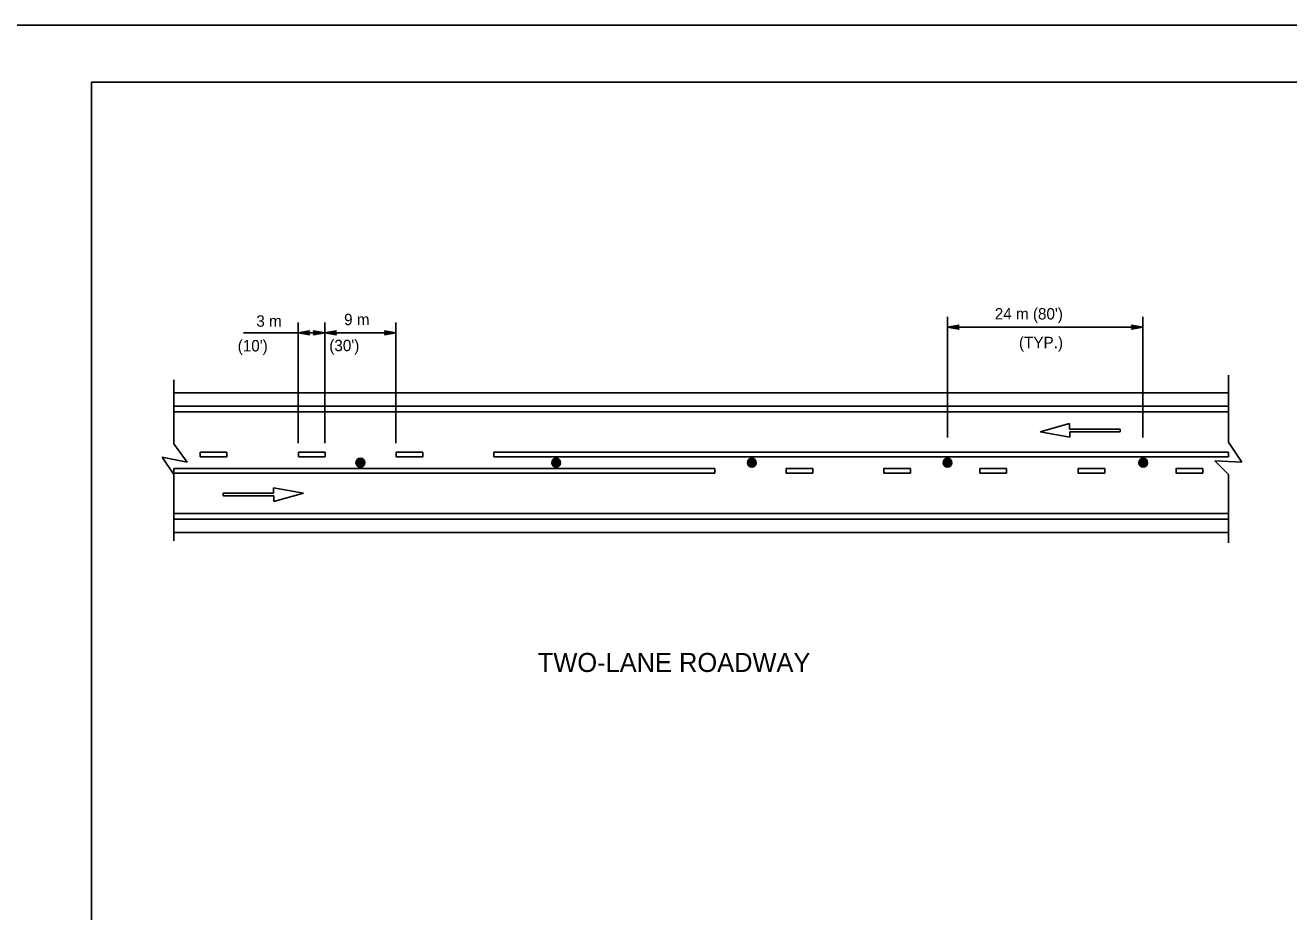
# Model space of a CAD drawing. Extents: x 639362 to 641108, y 298458 to 299646.
# Drawn here: x 640225.9 to 640558.2, y 299412.4 to 299645.6 of the extents above; entities that cross this region are included whole.
import ezdxf

# ---------------------------------------------------------------- set-up
doc = ezdxf.new("R2010")
doc.units = 0
for name, color, linetype in [('1', 7, 'Continuous'), ('2', 7, 'Continuous'), ('3', 7, 'Continuous'), ('PLT-BNDY', 7, 'Continuous')]:
    doc.layers.add(name, color=color, linetype=linetype)

# ---------------------------------------------------------------- blocks, each defined once
blk = doc.blocks.new('RARROW')
at = {"layer": '3'}
blk.add_lwpolyline([(-2.2695, 0.285), (-2.184875, 0.12075), (0, 0), (-2.2695, 0.285), (-2.38575, 0.384625), (0, 0), (-2.183125, -0.108), (-2.262875, -0.2705), (0, 0), (-2.38575, -0.379125), (-2.262875, -0.2705)], dxfattribs=at)

msp = doc.modelspace()

# ---------------------------------------------------------------- linework, layer by layer
at = {"layer": '1'}
for q in [(641029.31, 299630.63), (640243.31, 299066.63)]:
    msp.add_line((640243.31, 299630.63), q, dxfattribs=at)
at = {"layer": '2'}
for p, q in [((640468.44, 299537.15), (640468.44, 299568.92)), ((640519.83, 299537.15), (640519.83, 299568.92)), ((640283.3, 299564.71), (640304.65, 299564.71)), ((640297.63, 299535.66), (640297.63, 299567.43)), ((640304.65, 299535.66), (640304.65, 299567.43)), ((640304.65, 299564.71), (640323.37, 299564.71)), ((640323.37, 299535.66), (640323.37, 299567.43)), ((640519.83, 299566.2), (640468.44, 299566.2)), ((640264.93, 299552.35), (640264.93, 299535.55)), ((640542.37, 299553.63), (640542.37, 299535.95)), ((640264.93, 299548.92), (640542.37, 299548.92)), ((640264.93, 299545.42), (640542.37, 299545.42)), ((640264.93, 299543.92), (640542.37, 299543.92)), ((640500.53, 299540.83), (640492.81, 299538.71)), ((640492.81, 299538.71), (640500.61, 299537.24)), ((640500.53, 299539.38), (640500.53, 299540.83)), ((640513.86, 299539.38), (640500.53, 299539.38)), ((640500.61, 299537.24), (640500.61, 299538.68)), ((640500.61, 299538.68), (640513.86, 299538.68)), ((640513.86, 299538.68), (640513.86, 299539.38)), ((640268.42, 299530.66), (640264.93, 299535.55)), ((640545.86, 299530.66), (640542.37, 299535.95)), ((640264.93, 299527.43), (640261.88, 299532.01)), ((640261.88, 299532.01), (640268.42, 299530.66)), ((640278.91, 299533.35), (640271.89, 299533.35)), ((640271.89, 299533.35), (640278.91, 299533.33)), ((640278.91, 299532.13), (640278.91, 299533.35)), ((640304.76, 299533.35), (640297.74, 299533.35)), ((640297.74, 299533.35), (640304.76, 299533.33)), ((640304.76, 299532.13), (640304.76, 299533.35)), ((640330.42, 299533.35), (640323.41, 299533.35)), ((640323.41, 299533.35), (640330.42, 299533.33)), ((640330.42, 299532.13), (640330.42, 299533.35)), ((640542.37, 299533.33), (640349.14, 299533.33)), ((640349.14, 299533.33), (640349.14, 299532.13)), ((640349.14, 299532.13), (640542.37, 299532.13)), ((640542.37, 299532.13), (640542.37, 299533.33)), ((640407.24, 299529.02), (640264.97, 299529.02)), ((640264.97, 299529.02), (640264.97, 299527.82)), ((640407.24, 299527.82), (640407.24, 299529.02)), ((640433, 299529.04), (640425.98, 299529.04)), ((640425.98, 299529.04), (640433, 299529.02)), ((640433, 299527.82), (640433, 299529.04)), ((640458.68, 299529.04), (640451.66, 299529.04)), ((640451.66, 299529.04), (640458.68, 299529.02)), ((640458.68, 299527.82), (640458.68, 299529.04)), ((640484, 299529.04), (640476.98, 299529.04)), ((640476.98, 299529.04), (640484, 299529.02)), ((640484, 299527.82), (640484, 299529.04)), ((640509.8, 299529.04), (640502.78, 299529.04)), ((640502.78, 299529.04), (640509.8, 299529.02)), ((640509.8, 299527.82), (640509.8, 299529.04)), ((640535.59, 299529.04), (640528.57, 299529.04)), ((640528.57, 299529.04), (640535.59, 299529.02)), ((640535.59, 299527.82), (640535.59, 299529.04)), ((640542.37, 299527.43), (640538.76, 299531.05)), ((640538.76, 299531.05), (640545.86, 299530.66)), ((640264.93, 299527.43), (640264.93, 299509.98)), ((640264.97, 299527.82), (640407.24, 299527.82)), ((640542.37, 299527.43), (640542.37, 299509.46)), ((640291.19, 299522.54), (640277.95, 299522.54)), ((640277.95, 299522.54), (640277.95, 299521.84)), ((640277.95, 299521.84), (640291.27, 299521.84)), ((640299, 299522.51), (640291.19, 299523.98)), ((640291.19, 299523.98), (640291.19, 299522.54)), ((640291.27, 299520.39), (640299, 299522.51)), ((640291.27, 299521.84), (640291.27, 299520.39)), ((640264.93, 299517.23), (640542.37, 299517.23)), ((640264.93, 299515.73), (640542.37, 299515.73)), ((640264.93, 299512.23), (640542.37, 299512.23))]:
    msp.add_line(p, q, dxfattribs=at)
for points in [[(640278.91, 299533.33), (640271.89, 299533.33), (640271.89, 299532.13), (640278.91, 299532.13)], [(640304.76, 299533.33), (640297.74, 299533.33), (640297.74, 299532.13), (640304.76, 299532.13)], [(640330.42, 299533.33), (640323.41, 299533.33), (640323.41, 299532.13), (640330.42, 299532.13)], [(640433, 299529.02), (640425.98, 299529.02), (640425.98, 299527.82), (640433, 299527.82)], [(640458.68, 299529.02), (640451.66, 299529.02), (640451.66, 299527.82), (640458.68, 299527.82)], [(640484, 299529.02), (640476.98, 299529.02), (640476.98, 299527.82), (640484, 299527.82)], [(640509.8, 299529.02), (640502.78, 299529.02), (640502.78, 299527.82), (640509.8, 299527.82)], [(640535.59, 299529.02), (640528.57, 299529.02), (640528.57, 299527.82), (640535.59, 299527.82)]]:
    msp.add_lwpolyline(points, dxfattribs=at)
for centre, radius in [((640314, 299530.57), 1.15), ((640314, 299530.57), 1.07), ((640314, 299530.57), 0.985), ((640314, 299530.57), 0.904), ((640314, 299530.57), 0.822), ((640365.49, 299530.57), 1.15), ((640365.49, 299530.57), 1.07), ((640365.49, 299530.57), 0.985), ((640365.49, 299530.57), 0.904), ((640365.49, 299530.57), 0.822), ((640416.97, 299530.57), 1.15), ((640416.97, 299530.57), 1.07), ((640416.97, 299530.57), 0.985), ((640416.97, 299530.57), 0.904), ((640416.97, 299530.57), 0.822), ((640468.45, 299530.57), 1.15), ((640468.45, 299530.57), 1.07), ((640468.45, 299530.57), 0.985), ((640468.45, 299530.57), 0.904), ((640468.45, 299530.57), 0.822), ((640519.94, 299530.57), 1.15), ((640519.94, 299530.57), 1.07), ((640519.94, 299530.57), 0.985), ((640519.94, 299530.57), 0.904), ((640519.94, 299530.57), 0.822), ((640314, 299530.57), 0.741), ((640314, 299530.57), 0.659), ((640314, 299530.57), 0.578), ((640314, 299530.57), 0.496), ((640314, 299530.57), 0.414), ((640314, 299530.57), 0.333), ((640314, 299530.57), 0.251), ((640314, 299530.57), 0.17), ((640314, 299530.57), 0.0881), ((640365.49, 299530.57), 0.741), ((640365.49, 299530.57), 0.659), ((640365.49, 299530.57), 0.578), ((640365.49, 299530.57), 0.496), ((640365.49, 299530.57), 0.414), ((640365.49, 299530.57), 0.333), ((640365.49, 299530.57), 0.251), ((640365.49, 299530.57), 0.17), ((640365.49, 299530.57), 0.0881), ((640416.97, 299530.57), 0.741), ((640416.97, 299530.57), 0.659), ((640416.97, 299530.57), 0.578), ((640416.97, 299530.57), 0.496), ((640416.97, 299530.57), 0.414), ((640416.97, 299530.57), 0.333), ((640416.97, 299530.57), 0.251), ((640416.97, 299530.57), 0.17), ((640416.97, 299530.57), 0.0881), ((640468.45, 299530.57), 0.741), ((640468.45, 299530.57), 0.659), ((640468.45, 299530.57), 0.578), ((640468.45, 299530.57), 0.496), ((640468.45, 299530.57), 0.414), ((640468.45, 299530.57), 0.333), ((640468.45, 299530.57), 0.251), ((640468.45, 299530.57), 0.17), ((640468.45, 299530.57), 0.0881), ((640519.94, 299530.57), 0.741), ((640519.94, 299530.57), 0.659), ((640519.94, 299530.57), 0.578), ((640519.94, 299530.57), 0.496), ((640519.94, 299530.57), 0.414), ((640519.94, 299530.57), 0.333), ((640519.94, 299530.57), 0.251), ((640519.94, 299530.57), 0.17), ((640519.94, 299530.57), 0.0881)]:
    msp.add_circle(centre, radius, dxfattribs=at)
at = {"layer": 'PLT-BNDY'}
msp.add_lwpolyline([(640203.31, 299645.63), (641044.31, 299645.63), (641044.31, 299051.63), (640203.31, 299051.63)], close=True, dxfattribs=at)

# ---------------------------------------------------------------- block references
at = {"layer": '2', "xscale": 1.2574347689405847, "yscale": 1.3092961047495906, "rotation": 180}
for p in [(640297.63, 299564.71), (640304.65, 299564.71), (640468.44, 299566.2)]:
    msp.add_blockref('RARROW', p, dxfattribs=at)
at = {"layer": '2', "xscale": 1.2574347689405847, "yscale": 1.3092961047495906}
for p in [(640304.65, 299564.71), (640323.37, 299564.71), (640519.83, 299566.2)]:
    msp.add_blockref('RARROW', p, dxfattribs=at)

# ---------------------------------------------------------------- texts
at = {"layer": '2'}
for s, height, p in [("24 m (80')", 3, (640480.87, 299568.23)), ('3 m ', 3, (640286.64, 299566.33)), ('9 m', 3, (640309.72, 299566.74)), (" (10')", 3, (640280.62, 299559.83)), (" (30')", 3, (640304.71, 299559.9)), ('(TYP.)', 3, (640487.24, 299560.68)), ('TWO-LANE ROADWAY', 5, (640360.68, 299475.52))]:
    msp.add_text(s, height=height, dxfattribs=at).set_placement(p)

doc.saveas('drawing.dxf')
